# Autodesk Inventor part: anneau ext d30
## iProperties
Author: chr
Created: 2002-03
Part Number: anneau ext d30
Material: Par défaut
Document SubType Name: Modélisation
Designer: chr
Control State: 0
Master: False
Checked Out: False
PropertySet Name: Design Tracking Control
Shininess: 20.0
Angle Display Precision: 2
Document Length Units: 11269
Document Angle Units: 11283
Document Time Units: 11279
Document Mass Units: 11290
Document Length Units Precision: 3
Document Angle Units Precision: 2
Compacted: False
PropertySet Name: _Private Model Information
Density: 0.0
Volumn: 0.0
Area: 0.0
PropertySet Name: Model Information
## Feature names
1. Base1
